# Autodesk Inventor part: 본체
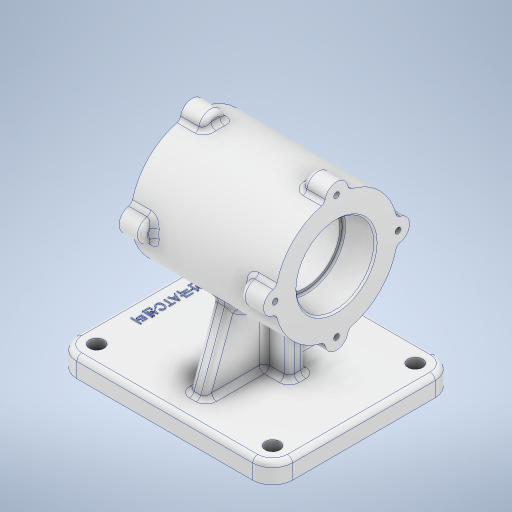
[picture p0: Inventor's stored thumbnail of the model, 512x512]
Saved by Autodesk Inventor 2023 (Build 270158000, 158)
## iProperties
Created: 2023-08
Part Number: 본체
Material: 알루미늄 6061
Document SubType Name: Modeling
Designer: asung
Density: 2.7 g/cm^3
Appearance: 알루미늄 - 평지
Mass: 1215.13 g
Surface Area: 797.477 cm^2
Volume: 450.05 cm^3
Author: asung
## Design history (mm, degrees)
sketch "스케치1"
  geometry: L1 (53, -55)-(-53, -55); L2 (-65, -43)-(-65, 43); L3 (-53, 55)-(53, 55); L4 (65, 43)-(65, -43); L5 (65, -55)-(-65, 55); L6 (-65, -55)-(65, 55); C1 r 4.5 at (53, -43); C2 r 4.5 at (53, 43); C3 r 4.5 at (-53, -43); C4 r 4.5 at (-53, 43); A1 r 12 centre (53, 43) between (65, 43) and (53, 55); A2 r 12 centre (53, -43) between (53, -55) and (65, -43); A3 r 12 centre (-53, -43) between (-65, -43) and (-53, -55); A4 r 12 centre (-53, 43) between (-53, 55) and (-65, 43); 1 further point
  constraints: 12 end point, 8 centre point, 8 point on circle, 8 point on line, 8 tangent, 4 coincident, 3 equal radius, 2 midpoint, 2 parallel, 1 horizontal, 1 perpendicular
  dimensions: "d0" = 130 distance of L5.end L6.end; "d1" = 110 distance of L6.start L5.end; "d2" = 12 radius of A1; "d3" = 9 diameter of C1; "d4" = 9 diameter of C2; "d5" = 9 diameter of C3; "d6" = 9 diameter of C4
extrude "돌출1" new body sketch "스케치1" distance "d7" = 12; taper "d8" = 0 deg
node "작업 평면3"
sketch "스케치2"
  geometry: L1 (98, 12)-(98, 0) reference; L2 (98, 0)-(-12, 0) reference; L3 (-12, 0)-(-12, 12) reference; L4 (-12, 12)-(98, 12) reference; L5 (43, 0)-(43, 82); C1 r 37 at (43, 82)
  constraints: 2 end point, 1 centre point, 1 coincident, 1 vertical
  dimensions: "d11" = 82 distance of L5.start L5.end; "d12" = 37 radius of C1
extrude "돌출2" join sketch "스케치2" stored distance "d13" = 87; taper "d14" = 0 deg
sketch "스케치3"
  geometry: C1 r 37 at (0, 0) reference; 1 further point
hole "구멍1" sketch "스케치3" at (0, 0) diameter "d15" = 42; stored, may be unused: countersink angle "d19" = 90 deg, drill point angle "d21" = 0 deg; dims "d16" = 10, "d17" = 47, "d18" = 19, "d20" = 87
sketch "스케치4"
  geometry: C1 r 37 at (0, 0) reference; 2 further points
  constraints: 1 coincident
hole "구멍2" sketch "스케치4" at (0, 0) diameter "d22" = 42; stored, may be unused: countersink angle "d26" = 90 deg, drill point angle "d28" = 0 deg; dims "d23" = 6, "d24" = 47, "d25" = 19, "d27" = 87
chamfer "모따기1" distance "d29" = 1; stored, may be unused: second distance "d30" = 2, angle "d31" = 45 deg
fillet "모깎기1" dims "d32" = 1
sketch "스케치5"
  geometry: C1 r 24.5 at (0, 0) reference; C2 r 7 at (0, 37); 2 further points
  constraints: 1 centre point, 1 vertical alignment, 1 other
  dimensions: "d33" = 7 radius of C2
extrude "돌출3" join sketch "스케치5" distance "d34" = 14; taper "d35" = 0 deg
fillet "모깎기2" dims "d36" = 3
fillet "모깎기3" dims "d37" = 3
node "작업 평면4"
sketch "스케치6"
  geometry: C1 r 24.5 at (43, 82) reference; C2 r 37 at (43, 82); A1 r 37 centre (43, 82) between (78.863, 91.104) and (52.104, 117.863) reference; A2 r 3 centre (52.842, 120.77) between (49.889, 120.239) and (52.104, 117.863) reference; A3 r 7 centre (43, 119) between (49.889, 120.239) and (36.111, 120.239) reference; A4 r 3 centre (33.158, 120.77) between (33.896, 117.863) and (36.111, 120.239) reference; A5 r 37 centre (43, 82) between (33.896, 117.863) and (7.137, 91.104) reference; A6 r 3 centre (4.23, 91.842) between (4.761, 88.889) and (7.137, 91.104) reference; A7 r 7 centre (6, 82) between (4.761, 88.889) and (4.761, 75.111) reference; A8 r 3 centre (4.23, 72.158) between (7.137, 72.896) and (4.761, 75.111) reference; A9 r 37 centre (43, 82) between (7.137, 72.896) and (33.896, 46.138) reference; A10 r 3 centre (33.158, 43.23) between (36.111, 43.761) and (33.896, 46.138) reference; A11 r 7 centre (43, 45) between (36.111, 43.761) and (49.889, 43.761) reference; A12 r 3 centre (52.842, 43.23) between (52.104, 46.138) and (49.889, 43.761) reference; A13 r 37 centre (43, 82) between (52.104, 46.138) and (78.863, 72.896) reference; A14 r 3 centre (81.77, 72.158) between (81.239, 75.111) and (78.863, 72.896) reference; A15 r 7 centre (80, 82) between (81.239, 75.111) and (81.239, 88.889) reference; A16 r 3 centre (81.77, 91.842) between (78.863, 91.104) and (81.239, 88.889) reference; 2 further points
  constraints: 2 coincident, 1 centre point
  dimensions: "d41" = 37 radius of C2
hole "구멍3" sketch "스케치6" at (43, 119) diameter "d42" = 3.45873; stored, may be unused: countersink angle "d46" = 90 deg, drill point angle "d48" = 118 deg; dims "d43" = 8, "d44" = 47, "d45" = 19, "d47" = 10
sketch "스케치7"
  geometry: L1 (-15, 5)-(25, 5); L2 (25, 5)-(25, -5); L3 (25, -5)-(-15, -5); L4 (-15, -5)-(-15, 5); L5 (-65, 43)-(-65, -43) reference; 4 further points
  constraints: 8 end point, 3 midpoint, 2 parallel, 1 horizontal, 1 perpendicular
  dimensions: "d52" = 40 distance of L2.end L3.end; "d53" = 10 distance of L1.end L2.end; "d54" = 70 distance from line of L5 point (5, 5); "d55" = 0 vertical distance of point (-65, 0) point (-15, 0)
extrude "돌출4" join sketch "스케치7" stored distance "d56" = 14; taper "d57" = 0 deg
sketch "스케치8"
  geometry: L1 (98, 12)-(98, 0) reference; L2 (98, 0)-(-12, 0) reference; L3 (-12, 0)-(-12, 12) reference; L4 (-12, 12)-(38, 12) reference; L5 (38, 12)-(38, 45.339) reference; L6 (48, 45.339)-(48, 12) reference; L7 (48, 12)-(98, 12) reference; L8 (81.5, 12)-(90.5, 12) reference; L9 (84, 12)-(68.336, 55.036); L10 (-4.5, 12)-(4.5, 12) reference; L11 (2, 12)-(17.664, 55.036); C1 r 21 at (43, 82) reference; A1 r 37 centre (43, 82) between (48, 45.339) and (38, 45.339) reference; 1 further point
  constraints: 4 end point, 2 point on circle, 2 point on line
  dimensions: "d58" = 14 distance from line of L1 L9.start; "d59" = 14 distance from line of L3 L11.start; "d60" = 110 deg angle of L7 L9; "d61" = 110 deg angle of L4 L11
  node "절단 모서리 투영2"
feature "리브1" dims "d62" = 1, "d63" = 10, "d64" = 0, "d65" = 0, "d66" = 1, "d67" = 1
feature "리브2" dims "d68" = 1, "d69" = 10, "d70" = 0, "d71" = 0, "d72" = 1, "d73" = 1
fillet "모깎기4" dims "d74" = 3
fillet "모깎기5" dims "d75" = 3
sketch "스케치9"
  geometry: L1 (-62, -43)-(-62, 43) reference; L2 (3, -43.101)-(7, -43.101) reference; 4 further points
  constraints: 2 midpoint, 1 horizontal alignment, 1 other
  dimensions: "d76" = 58 horizontal distance of point (5, -43.101) point (-53, 0)
feature "엠보싱1" sketch "스케치9" dims "d0" = 130, "d1" = 110, "d2" = 12, "d3" = 9, "d4" = 9, "d5" = 9, "d6" = 9, "d77" = 0.5, "d78" = 0
feature "Σ耀Υ耀Χ耀Ω耀Ϋ耀έ耀ί耀α耀" dims "d0" = 130, "d1" = 110, "d2" = 12, "d3" = 9, "d4" = 9, "d5" = 9, "d6" = 9, "d7" = 12, "d8" = 0, "d10" = -70, "d11" = 82, "d12" = 37, "d13" = 87, "d14" = 0, "d15" = 42, "d16" = 10, "d17" = 47, "d18" = 19, "d19" = 90 deg, "d20" = 87, "d21" = 0, "d22" = 42, "d23" = 6, "d24" = 47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
node "솔리드1"
pattern_circular "원형 패턴1" dims angle "d39" = 360 deg
mirror "미러1"
pattern_circular "원형 패턴2" dims angle "d50" = 360 deg
mirror "미러2"
node "투영된 루프1"
node "투영된 루프2"
node "투영된 루프3"
node "절단 모서리 투영1"
feature "A9D066F2-1C7D-4E18-AEED-F7BC21143FA4" dims "d15" = 42, "d16" = 10, "d17" = 47, "d18" = 19, "d19" = 90 deg, "d20" = 87, "d21" = 0
